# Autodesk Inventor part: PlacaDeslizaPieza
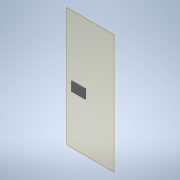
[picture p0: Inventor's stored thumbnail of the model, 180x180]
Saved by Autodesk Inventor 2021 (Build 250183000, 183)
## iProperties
Created: 2021-02
Part Number: PlacaDeslizaPieza
Material: Genérico
Document SubType Name: Modeling
Designer: ATOUZA
Density: 1 g/cm^3
Appearance: Valor por defecto
Author: ATOUZA
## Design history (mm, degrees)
node "Plano de trabajo1"
extrude "Extrusión1" new body sketch "Boceto1" distance "d1" = 5; taper "d2" = 0 deg
fillet "Empalme1" dims "d3" = 4
node "Sólido1"
